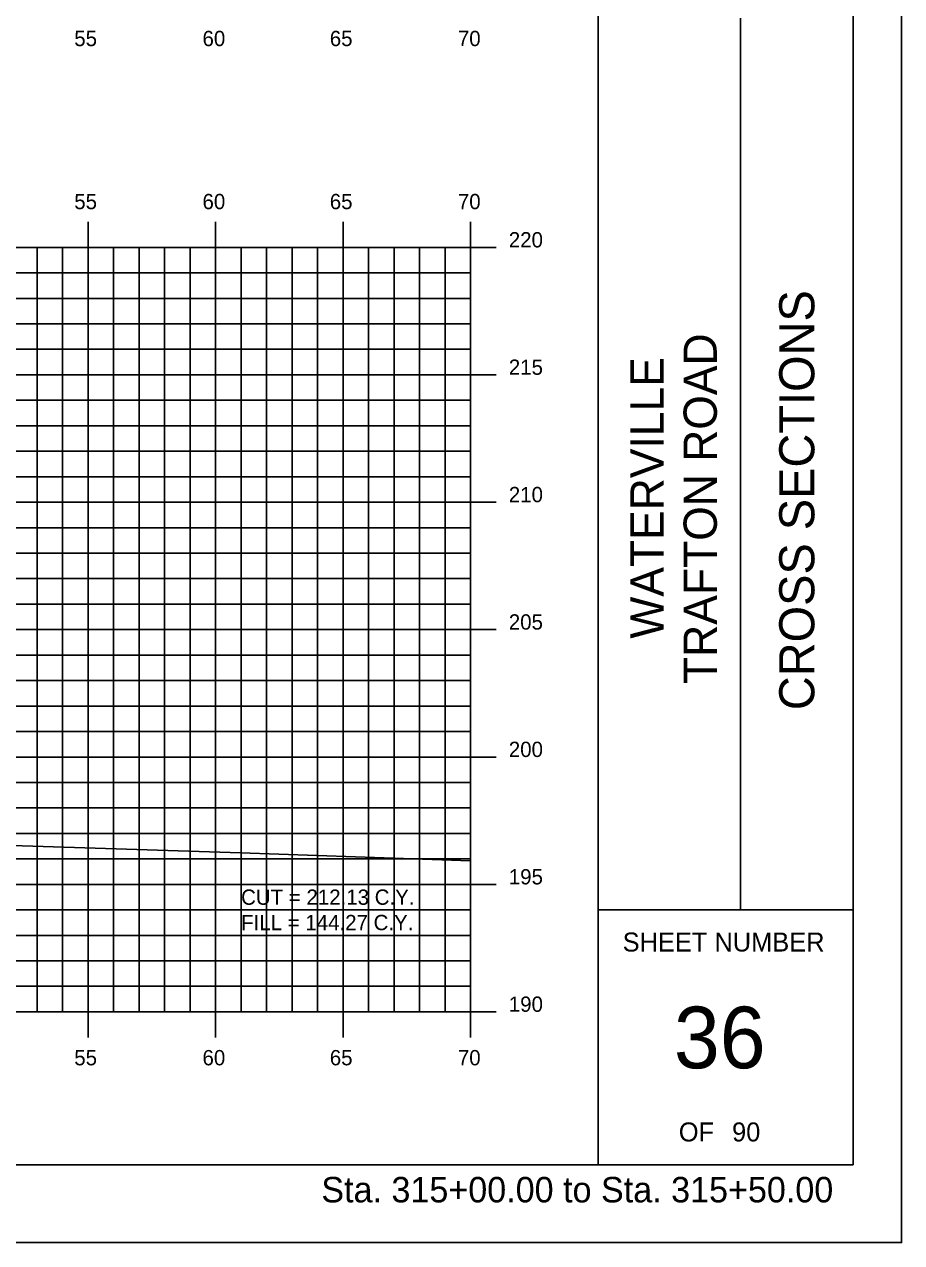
# Model space of a CAD drawing. Extents: x 1138541 to 1138711, y 608981 to 609091.
# Drawn here: x 1138676.94 to 1138711.34, y 608981.28 to 609029.09 of the extents above; entities that cross this region are included whole.
import ezdxf

# ---------------------------------------------------------------- set-up
doc = ezdxf.new("R2010")
doc.units = 0
for name, color, linetype in [('BORDER', 7, 'Continuous'), ('D_Text_Standard', 7, 'Continuous'), ('H_V ANNOTATION', 7, 'Continuous'), ('HIGHWAY_TITLE', 7, 'Continuous'), ('MAJOR', 7, 'Continuous'), ('MINOR', 7, 'Continuous'), ('PLOT BOUNDARY', 7, 'Continuous'), ('S_Roadway_Centerline', 7, 'Continuous')]:
    doc.layers.add(name, color=color, linetype=linetype)

msp = doc.modelspace()

# ---------------------------------------------------------------- linework, layer by layer
at = {"layer": 'BORDER'}
for p, q in [((1138699.436, 608984.335), (1138699.436, 609089.335)), ((1138705.027, 608994.338), (1138705.027, 609029.338)), ((1138699.436, 608994.338), (1138709.436, 608994.338))]:
    msp.add_line(p, q, dxfattribs=at)
msp.add_lwpolyline([(1138549.436, 608984.335), (1138709.436, 608984.335), (1138709.436, 609089.335), (1138549.436, 609089.335)], close=True, dxfattribs=at)
at = {"layer": 'MAJOR'}
for p, q in [((1138679.436, 609021.337), (1138679.436, 609020.335)), ((1138684.436, 609021.337), (1138684.436, 609020.335)), ((1138689.436, 609021.337), (1138689.436, 609020.335)), ((1138694.436, 609021.337), (1138694.436, 609020.335)), ((1138554.436, 609020.335), (1138694.436, 609020.335)), ((1138554.436, 609020.335), (1138694.436, 609020.335)), ((1138679.436, 608990.335), (1138679.436, 609020.335)), ((1138684.436, 608990.335), (1138684.436, 609020.335)), ((1138689.436, 608990.335), (1138689.436, 609020.335)), ((1138695.438, 609020.335), (1138693.434, 609020.335)), ((1138694.436, 608990.335), (1138694.436, 609020.335)), ((1138694.436, 608990.335), (1138694.436, 609020.335)), ((1138554.436, 609015.335), (1138694.436, 609015.335)), ((1138695.438, 609015.335), (1138693.434, 609015.335)), ((1138554.436, 609010.335), (1138694.436, 609010.335)), ((1138695.438, 609010.335), (1138693.434, 609010.335)), ((1138554.436, 609005.335), (1138694.436, 609005.335)), ((1138695.438, 609005.335), (1138693.434, 609005.335)), ((1138554.436, 609000.335), (1138694.436, 609000.335)), ((1138695.438, 609000.335), (1138693.434, 609000.335)), ((1138554.436, 608995.335), (1138694.436, 608995.335)), ((1138695.438, 608995.335), (1138693.434, 608995.335)), ((1138554.436, 608990.335), (1138694.436, 608990.335)), ((1138554.436, 608990.335), (1138694.436, 608990.335)), ((1138679.436, 608989.333), (1138679.436, 608990.335)), ((1138684.436, 608989.333), (1138684.436, 608990.335)), ((1138689.436, 608989.333), (1138689.436, 608990.335)), ((1138695.438, 608990.335), (1138693.434, 608990.335)), ((1138694.436, 608989.333), (1138694.436, 608990.335))]:
    msp.add_line(p, q, dxfattribs=at)
at = {"layer": 'MINOR'}
for p, q in [((1138677.436, 608990.335), (1138677.436, 609020.335)), ((1138678.436, 608990.335), (1138678.436, 609020.335)), ((1138680.436, 608990.335), (1138680.436, 609020.335)), ((1138681.436, 608990.335), (1138681.436, 609020.335)), ((1138682.436, 608990.335), (1138682.436, 609020.335)), ((1138683.436, 608990.335), (1138683.436, 609020.335)), ((1138685.436, 608990.335), (1138685.436, 609020.335)), ((1138686.436, 608990.335), (1138686.436, 609020.335)), ((1138687.436, 608990.335), (1138687.436, 609020.335)), ((1138688.436, 608990.335), (1138688.436, 609020.335)), ((1138690.436, 608990.335), (1138690.436, 609020.335)), ((1138691.436, 608990.335), (1138691.436, 609020.335)), ((1138692.436, 608990.335), (1138692.436, 609020.335)), ((1138693.436, 608990.335), (1138693.436, 609020.335)), ((1138554.436, 609019.335), (1138694.436, 609019.335)), ((1138694.436, 609019.335), (1138693.434, 609019.335)), ((1138554.436, 609018.335), (1138694.436, 609018.335)), ((1138694.436, 609018.335), (1138693.434, 609018.335)), ((1138554.436, 609017.335), (1138694.436, 609017.335)), ((1138694.436, 609017.335), (1138693.434, 609017.335)), ((1138554.436, 609016.335), (1138694.436, 609016.335)), ((1138694.436, 609016.335), (1138693.434, 609016.335)), ((1138554.436, 609014.335), (1138694.436, 609014.335)), ((1138694.436, 609014.335), (1138693.434, 609014.335)), ((1138554.436, 609013.335), (1138694.436, 609013.335)), ((1138694.436, 609013.335), (1138693.434, 609013.335)), ((1138554.436, 609012.335), (1138694.436, 609012.335)), ((1138694.436, 609012.335), (1138693.434, 609012.335)), ((1138554.436, 609011.335), (1138694.436, 609011.335)), ((1138694.436, 609011.335), (1138693.434, 609011.335)), ((1138554.436, 609009.335), (1138694.436, 609009.335)), ((1138694.436, 609009.335), (1138693.434, 609009.335)), ((1138554.436, 609008.335), (1138694.436, 609008.335)), ((1138694.436, 609008.335), (1138693.434, 609008.335)), ((1138554.436, 609007.335), (1138694.436, 609007.335)), ((1138694.436, 609007.335), (1138693.434, 609007.335)), ((1138554.436, 609006.335), (1138694.436, 609006.335)), ((1138694.436, 609006.335), (1138693.434, 609006.335)), ((1138554.436, 609004.335), (1138694.436, 609004.335)), ((1138694.436, 609004.335), (1138693.434, 609004.335)), ((1138554.436, 609003.335), (1138694.436, 609003.335)), ((1138694.436, 609003.335), (1138693.434, 609003.335)), ((1138554.436, 609002.335), (1138694.436, 609002.335)), ((1138694.436, 609002.335), (1138693.434, 609002.335)), ((1138554.436, 609001.335), (1138694.436, 609001.335)), ((1138694.436, 609001.335), (1138693.434, 609001.335)), ((1138554.436, 608999.335), (1138694.436, 608999.335)), ((1138694.436, 608999.335), (1138693.434, 608999.335)), ((1138554.436, 608998.335), (1138694.436, 608998.335)), ((1138694.436, 608998.335), (1138693.434, 608998.335)), ((1138554.436, 608997.335), (1138694.436, 608997.335)), ((1138694.436, 608997.335), (1138693.434, 608997.335)), ((1138554.436, 608996.335), (1138694.436, 608996.335)), ((1138694.436, 608996.335), (1138693.434, 608996.335)), ((1138554.436, 608994.335), (1138694.436, 608994.335)), ((1138694.436, 608994.335), (1138693.434, 608994.335)), ((1138554.436, 608993.335), (1138694.436, 608993.335)), ((1138694.436, 608993.335), (1138693.434, 608993.335)), ((1138554.436, 608992.335), (1138694.436, 608992.335)), ((1138694.436, 608992.335), (1138693.434, 608992.335)), ((1138554.436, 608991.335), (1138694.436, 608991.335)), ((1138694.436, 608991.335), (1138693.434, 608991.335))]:
    msp.add_line(p, q, dxfattribs=at)
at = {"layer": 'PLOT BOUNDARY'}
msp.add_lwpolyline([(1138541.342, 608981.276), (1138711.342, 608981.276), (1138711.342, 609091.276), (1138541.342, 609091.276)], close=True, dxfattribs=at)
at = {"layer": 'S_Roadway_Centerline'}
msp.add_lwpolyline([(1138638.229, 609012.472), (1138646.037, 609008.404), (1138655.547, 609003.497), (1138667.798, 608997.142), (1138667.879, 608997.141), (1138670.921, 608997.065), (1138674.795, 608996.915), (1138680.938, 608996.715), (1138685.408, 608996.58), (1138694.436, 608996.256)], dxfattribs=at)

# ---------------------------------------------------------------- texts
at = {"layer": 'BORDER'}
msp.add_text('CROSS SECTIONS', height=1.37787, rotation=90, dxfattribs=at).set_placement((1138707.92, 609002.172))
for s, height, p in [('SHEET NUMBER', 0.74527, (1138700.401, 608992.701)), ('36', 2.4194, (1138702.411, 608988.118)), ('OF', 0.7453, (1138702.603, 608985.248)), ('90', 0.7453, (1138704.692, 608985.248))]:
    msp.add_text(s, height=height, dxfattribs=at).set_placement(p)
at = {"layer": 'D_Text_Standard'}
for s, p in [('CUT = 212.13 C.Y.', (1138685.436, 608994.535)), ('FILL = 144.27 C.Y.', (1138685.436, 608993.539))]:
    msp.add_text(s, height=0.6, dxfattribs=at).set_placement(p)
at = {"layer": 'H_V ANNOTATION'}
for s, height, p in [('55', 0.6, (1138678.892, 609028.235)), ('60', 0.6, (1138683.922, 609028.235)), ('65', 0.6, (1138688.914, 609028.235)), ('70', 0.6, (1138693.938, 609028.235)), ('55', 0.6, (1138678.892, 609021.835)), ('60', 0.6, (1138683.922, 609021.835)), ('65', 0.6, (1138688.914, 609021.835)), ('70', 0.6, (1138693.938, 609021.835)), ('220', 0.6, (1138695.936, 609020.335)), ('215', 0.6, (1138695.936, 609015.335)), ('210', 0.6, (1138695.936, 609010.335)), ('205', 0.6, (1138695.936, 609005.335)), ('200', 0.6, (1138695.936, 609000.335)), ('195', 0.6, (1138695.936, 608995.335)), ('190', 0.6, (1138695.936, 608990.335)), ('55', 0.6, (1138678.892, 608988.235)), ('60', 0.6, (1138683.922, 608988.235)), ('65', 0.6, (1138688.914, 608988.235)), ('70', 0.6, (1138693.938, 608988.235)), ('Sta. 315+00.00 to Sta. 315+50.00', 1.0002, (1138688.582, 608982.855))]:
    msp.add_text(s, height=height, dxfattribs=at).set_placement(p)
at = {"layer": 'HIGHWAY_TITLE'}
for s, height, p in [('TRAFTON ROAD', 1.30428, (1138704.095, 609003.201)), ('WATERVILLE', 1.3043, (1138702.008, 609004.98))]:
    msp.add_text(s, height=height, rotation=90, dxfattribs=at).set_placement(p)

doc.saveas('drawing.dxf')
